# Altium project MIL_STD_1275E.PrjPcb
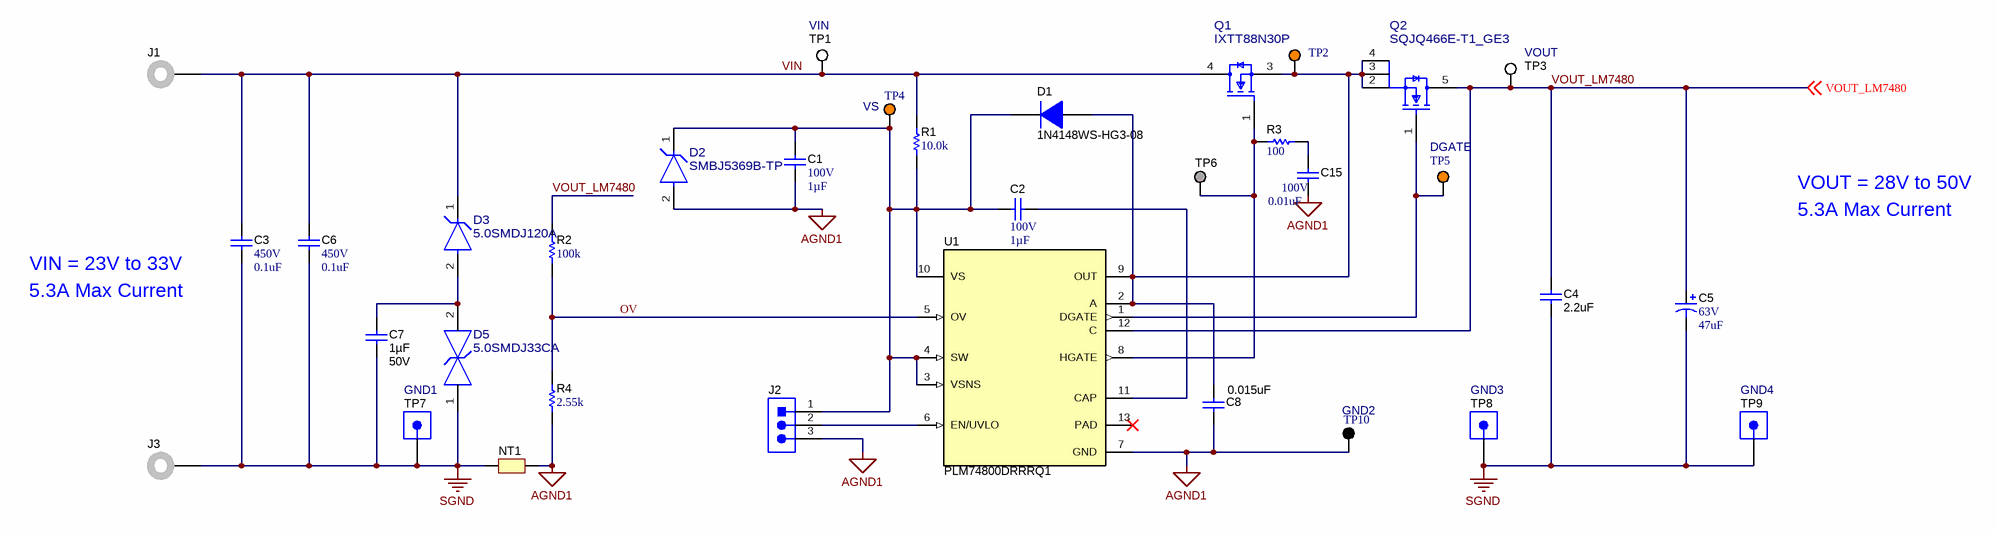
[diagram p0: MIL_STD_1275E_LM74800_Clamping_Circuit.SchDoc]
CopyrightYear: 2018; PCB_Layout: Albert Lo; PCB_Rev: E2; PRJ_Customer: Public Release; PRJ_Engineer: Albert Lo; PRJ_Number: MILSTD1275E; PRJ_Title: Change in menu Project|Project Options|Parameters; SCH_Rev: E2; TechSupport: http://www.ti.com/support; TID: N/A
3 sheets, 68 parts. Net scope: global (net labels, ports and power ports of the same name join across sheets).
Board file: MIL_STD_1275E.PcbDoc
Sheets:
  MIL_STD_1275E_LM74800_Clamping_Circuit.SchDoc
  MIL_STD_1275E_Hardware.SchDoc
  MIL_STD_1275E_LM5069_Clamping_Circuit.SchDoc

## Sheet MIL_STD_1275E_LM74800_Clamping_Circuit.SchDoc
size 431 x 279 mm; Date: Not shown in title block; ApprovedBy: Not shown in title block; CheckedBy: Not shown in title block; Author: Not shown in title block; CompanyName: Not shown in title block; Engineer: Not shown in title block; Organization: Not shown in title block; Address1: Not shown in title block; Address2: Not shown in title block; Address3: Not shown in title block; Address4: Not shown in title block; DocumentNumber: 1; Revision: Use project parameter SCH_Rev; SheetNumber: 1; SheetTotal: 4; PageSetup: Record=PageOptions¦CenterHorizontal=True¦CenterVertical=True¦PrintScale=1.00¦XCorrection=1.00¦YCorrection=1.00¦PrintKind=0¦BorderSize=5000000¦LeftOffset=0¦BottomOffset=0¦Orientation=2¦PaperLength=1000¦PaperWidth=1000¦Scale=100¦PaperSource=15¦PrintQuality=600¦MediaType=1¦DitherType=10¦PaperKind=Letter¦PrintScaleMode=1

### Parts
C1  VDC_V: 100V  Cap_F: 1µF  [0805_150]  (hidden comment: 08051C105K4Z2A)
C2  VDC_V: 100V  Cap_F: 1µF  [0805_150]  (hidden comment: 08051C105K4Z2A)
C3  VDC_V: 450V  ValueDisplayed: 0.1uF  [1206_180]  (hidden comment: C3216X7T2W104M160AE)
C4  ValueDisplayed: 2.2uF  [1210_210]  (hidden comment: CMP-0009084-1)
C5  VDC_V: 63V  ValueDisplayed: 47uF  [CAPSMT_62_HA0]  (hidden comment: EMVE630ADA470MHA0G)
C6  VDC_V: 450V  ValueDisplayed: 0.1uF  [1206_180]  (hidden comment: C3216X7T2W104M160AE)
C7  Cap_F: 1µF  VDC_V: 50V  [0805L]  (hidden comment: CGA4J3X7R1H105K125AB)
C8  value 0.015uF  [0603L]  (hidden comment: CGA3E2X7R2A153K080AA)
C15  VDC_V: 100V  ValueDisplayed: 0.01uF  [0402L]  (hidden comment: CGA2B3X7S2A103K050BB)
D1  1N4148WS-HG3-08  [SOD-323]
D2  SMBJ5369B-TP  [FP-SMBJ5369B-TP_SMB-MFG]
D3  5.0SMDJ120A  [FP-SMDJ120A_DO214AB-MFG]
D5  5.0SMDJ33CA  [FP-5.0SMDJ33CA_DO214AB-MFG]
J1  CMP-0055166-2  [Keystone575-8]  (value not drawn)
J2  PEC03SAAN  [CONN_PEC03SAAN]  (value not drawn)
J3  CMP-0055166-2  [Keystone575-8]  (value not drawn)
NT1  Net-Tie  [NetTie_0402]  (value not drawn)  (net tie, no BOM)
Q1  IXTT88N30P  [FP-IXTT88N30P_TO-268AA-IPC_C]
Q2  SQJQ466E-T1_GE3  [FP-SQJQ466E-T1_GE3_PowerPAK 8 x 8L-MFG]
R1  ValueDisplayed: 10.0k  [2512_084]  (hidden comment: HVCB2512FDD10K0)
R2  ValueDisplayed: 100k  [0402L]  (hidden comment: ERJ-2RKF1003X)
R3  ValueDisplayed: 100  [0402L]  (hidden comment: CRCW0402100RJNED)
R4  ValueDisplayed: 2.55k  [0402L]  (hidden comment: CRCW04022K55FKED)
TP1  Note: VIN  [Testpoint_Keystone_Miniature]  (hidden comment: 5015)
TP2  5003  [Keystone5003]  (value not drawn)
TP3  Note: VOUT  [Testpoint_Keystone_Miniature]  (hidden comment: 5015)
TP4  Note: VS  [Keystone5003]  (hidden comment: 5003)
TP5  Note: DGATE  [Keystone5003]  (hidden comment: 5003)
TP6  TP_SM_1MM  [TP_SM_1MM]  (value not drawn)  (no BOM)
TP7  Note: GND1  [CONN_1040]  (hidden comment: CMP-0055161-1)
TP8  Note: GND3  [CONN_1040]  (hidden comment: CMP-0055161-1)
TP9  Note: GND4  [CONN_1040]  (hidden comment: CMP-0055161-1)
TP10  Note: GND2  [Keystone5001]  (hidden comment: 5001)
U1  PLM74800DRRRQ1  [DRR0012E]

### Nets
AGND1: C1.2 C8.2 C15.2 D2.2(ANODE) J2.3 NT1.2 R4.1 TP10.1 U1.7(GND)
SGND: C3.2 C4.2 C5.2(-) C6.2 C7.2 D5.1 J3.1 NT1.1 TP7.1 TP8.1 TP9.1
OV: R2.1 R4.2 U1.5(OV)
VIN: C3.1 C6.1 D3.1(CATHODE) J1.1 Q1.4(Drain) R1.2 TP1.1
VOUT_LM7480: C4.1 C5.1(+) Q2.5(D) R2.2 TP3.1 U1.12(C) ; off-sheet VOUT_LM7480
NetC1_1: C1.1 C2.1 D1.1(K) D2.1(CATHODE) J2.1 R1.1 TP4.1 U1.3(VSNS) U1.4(SW) U1.10(VS)
NetC2_2: C2.2 U1.11(CAP)
NetC7_1: C7.1 D3.2(ANODE) D5.2
NetC8_1: C8.1 D1.2(A) Q1.3(Source) Q2.2(S) Q2.3(S) Q2.4(S) TP2.1 U1.2(A) U1.9(OUT)
NetC15_1: C15.1 R3.2
NetJ2_2: J2.2 U1.6(EN/UVLO)
NetQ1_1: Q1.1(Gate) R3.1 TP6.1 U1.8(HGATE)
NetQ2_1: Q2.1(G) TP5.1 U1.1(DGATE)

Not connected (* = marked no-connect by the designer): U1 13(PAD)*

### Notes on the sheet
- 5.3A Max Current
- VOUT = 28V to 50V
- VIN = 23V to 33V

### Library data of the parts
C1 C2 = CMP-0861070-1: CAP, CERM, 1 µF, 100 V,+/- 10%, X7R, AEC-Q200 Grade 1, 0805; Manufacturer: AVX; SizeZ_mm: 1.5; Polarized: N; TaMax_C: 125°C; TaMin_C: -55°C; Value: 1uF; AEC Qualified: Y; U/M: EA; AEC Grade: 1; Cap_Case: 0805; SizeX_mm: 2; SizeArea_mm2: 2.5; SizeAreaWB_mm2: 6.75; AEC Category: Q200; SizeY_mm: 1.25
C3 C6 = CMP-0008730-2: CAP, CERM, 0.1 uF, 450 V, +/- 20%, X7T, 1206; Manufacturer: TDK; TaMin_C: -55°C; Polarized: N; SizeAreaWB_mm2: 10.92; Value1: Unknown; U/M: EA; Value: 0.1uF; TaMax_C: 125°C; SizeZ_mm: 1.8; SizeX_mm: 3.2; SizeY_mm: 1.6; Cap_Case: 1206; SizeArea_mm2: 5.12; Cap_F: 100nF; AEC Category: Q200
C4 = CMP-0009084-1: CAP, CERM, 2.2 uF, 100 V, +/- 10%, X7R, 1210; PartNumber: C1210C225K1RACTU; Manufacturer: Kemet; Polarized: N; CompType: Capacitor; Value: 2.2uF; U/M: EA; Cap_F: 2.2µF; Value1: Unknown; VDC_V: 100V; TaMin_C: -55°C; TaMax_C: 125°C; Cap_Case: 1210; SizeArea_mm2: 8; SizeAreaWB_mm2: 14.7; SizeX_mm: 3.2; SizeY_mm: 2.5; SizeZ_mm: 2.1; AEC Category: Q200
C5 = CMP-0011301-2: CAP, AL, 47 uF, 63 V, +/- 20%, SMD; Manufacturer: Chemi-Con; TaMin_C: -40°C; Polarized: Y; SizeAreaWB_mm2: 106.09; Value1: Unknown; U/M: EA; Value: 47uF; TaMax_C: 105°C; SizeZ_mm: 10; SizeX_mm: 8.3; Cap_Case: HA0; SizeArea_mm2: 68.89; CompType: Capacitor; Cap_F: 47µF; IRMS_A: 170mA; AEC Category: Q200
C7 = CMP-0007976-2: CAP, CERM, 1 uF, 50 V, +/- 10%, X7R, AEC-Q200 Grade 1, 0805; Manufacturer: TDK; TaMin_C: -55°C; ESR_ohm: 8.782m; Polarized: N; SizeAreaWB_mm2: 6.75; Value1: 0.008782 ohm; U/M: EA; Value: 1uF; TaMax_C: 125°C; SizeZ_mm: 1.45; SizeX_mm: 2; SizeY_mm: 1.25; Cap_Case: 0805; SizeArea_mm2: 2.5; AEC Qualified: Y; IRMS_A: 2.20488A; AEC Grade: 1; AEC Category: Q200
C8 = CMP-0007084-4: CAP, CERM, 0.015 uF, 100 V, +/- 10%, X7R, AEC-Q200 Grade 1, 0603; Manufacturer: TDK; TaMin_C: -55°C; ESR_ohm: 0.128703; Polarized: N; SizeAreaWB_mm2: 4.68; Value1: 0.128703 ohm; U/M: EA; TaMax_C: 125°C; SizeZ_mm: 1; SizeX_mm: 1.6; SizeY_mm: 0.8; Cap_Case: 0603; Value2: 100V; SizeArea_mm2: 1.28; AEC Qualified: Y; Cap_F: 15nF; IRMS_A: 506.826mA; AEC Category: Q200
C15 = CMP-0006333-2: CAP, CERM, 0.01 uF, 100 V, +/- 10%, X7S, AEC-Q200 Grade 1, 0402; Manufacturer: TDK; TaMin_C: -55°C; ESR_ohm: 0.4102; Polarized: N; SizeAreaWB_mm2: 3; Value1: 0.410191 ohm; U/M: EA; Value: 0.01uF; TaMax_C: 125°C; SizeZ_mm: 0.6; SizeX_mm: 1; SizeY_mm: 0.5; Cap_Case: 0402; AEC Qualified: Y; Cap_F: 10nF; IRMS_A: 291.729mA; AEC Category: Q200
D1 = CMP-0860225-1: Diode, Switching, 100 V, 150 A, AEC-Q101, SOD-323; Manufacturer: Vishay-Semiconductor; Vf_V: 1.2V; TJmax_C: 150°C; Value: 100V; SizeX_mm: 2.7; SizeZ_mm: 1; Io_A: 150A; SizeAreaWB_mm2: 8.695; AEC Qualified: Y; SizeY_mm: 1.35; SizeArea_mm2: 3.645; AEC Category: Q101
D2 = CMP-0095181-1: Zener Diode 51 V 5 W ±5% Surface Mount DO-214AA (SMB); Manufacturer: MCC; Standoff Height: 0.05mm; Zener Impedance: 27Ω; AEC Qualified: No; Vr_V: 0.9V; SizeZ_mm: 2.62mm; Vz_V: 51V; Power_W: 5W; TJmax_C: +150°C; Forward Current: 1mA
D3 = CMP-0093492-1: Diode TVS Single Uni-Dir 120V 5KW 2-Pin DO-214AB; Manufacturer: Littelfuse Inc; Ipp: 26A; Direction: Unidirectional; AEC Qualified: No; TJmax_C: +150°C; Number Of Channels: 1; SizeZ_mm: 2.62mm; Breakdown Voltage: 133V; Clamping Voltage: 193V
D5 = CMP-0093617-1: 53.3V Clamp 93.9A Ipp Tvs Diode Surface Mount DO-214AB (SMCJ); Manufacturer: Littelfuse; Ppk: 5kW; AEC Qualified: No; VRWM: 33V; TJmax_C: +150°C; SizeZ_mm: 2.62mm; Breakdown Voltage: 36.7V; Number Of Channels: 1; Direction: Bidirectional
J1 J3 = CMP-0055166-2: Standard Banana Jack, Uninsulated, 8.9mm; PartNumber: 575-8; Manufacturer: Keystone; CT: TRUE; Green_REACh: Passed; CNHeader: FALSE; Green_Lifecycle: Active
J2 = CMP-0002338-1: Header, 100mil, 3x1, Tin, TH; Manufacturer: Sullins Connector Solutions; CNHeader: TRUE; Current_A: 3A; Green_Lifecycle: Not Set; Shrouded: N; Gender: Male; Green_REACh: Incomplete; Voltage_V: 1.8kV; Row_Count: 1; Pitch_mm: 2.54; CT: FALSE; Cert_UL: Y
NT1 = CMP-0078142-4: Single point connection between nets.
Q1 = CMP-0093697-1: N-Channel 300 V 88A (Tc) 600W (Tc) Surface Mount TO-268AA; Manufacturer: Littlefuse; VdsMax_V: 1.5V; QgTyp_nC: 180nC @ 10V; Transconductance: 60S; Turn On Delay Time: 25ns; Threshold Vgs Min: 2.5V; AEC Qualified: No; Reverse Recovery Time: 250ns; Vgs_V: 20V; SizeZ_mm: 5.35mm; Turn Off Delay Time: 96ns; Standoff Height: 0.02mm; Reverse Recovery Charge: 3300nC; ChMode: False; Rdson45_ohm: 40m; Threshold Vgs Max: 5V; TJmax_C: +150°C; Number Of N Channels: 1; Pulse Drain Current: 220A; Input Capacitace At Vds: 6300pF @ 25V; Drain To Source Breakdown Voltage: 300V
Q2 = CMP-0093493-1: N-Channel 60 V 200A (Tc) 150W (Tc) Surface Mount PowerPAK® 8 x 8; Manufacturer: Vishay; AEC Grade: Grade 0; Pulse Drain Current: 500A; SizeZ_mm: 2.03mm; Rthja Max: 50°C/W; TJmax_C: +175°C; Typ Forward Diode Voltage: 0.82V; Input Capacitace At Vds: 8170pF @ 25V; Vgs_V: 20V; Turn Off Delay Time: 47ns; VdsMax_V: 1.2V; Standoff Height: 0mm; AEC Qualified: Yes; Turn On Delay Time: 24ns; Number Of N Channels: 1; Drain To Source Breakdown Voltage: 60V; QgTyp_nC: 135nC @ 10V; ChMode: False; Transconductance: 140S; Threshold Vgs Min: 2.5V; Threshold Vgs Max: 3.5V; Rdson45_ohm: 1.7m
R1 = CMP-0015824-1: RES, 10.0 k, 1%, 2 W, 2512; Manufacturer: Stackpole Electronics Inc; Power_W: 2W; TempCo: 100 ppm/C; Value_Code: 10k0; U/M: EA; Value: 10.0k; EIA_Code: E96; Res_ohm: 10k; VDC_V: 2.5kV; AEC Category: Q200
R2 = CMP-0026659-2: RES, 100 k, 1%, 0.1 W, 0402; Manufacturer: Panasonic; Power_W: 100mW; TempCo: 100 ppm/C; U/M: EA; Value: 100k; EIA_Code: E96; SizeX_mm: 1; SizeY_mm: 0.5; SizeZ_mm: 0.6; Value2: 0.1W; AEC Qualified: Yes; VDC_V: 50V; AEC Category: Q200; AEC Grade: 0
R3 = CMP-0026824-3: RES, 100, 5%, 0.063 W, AEC-Q200 Grade 0, 0402; Manufacturer: Vishay-Dale; Power_W: 63mW; TempCo: 200 ppm/C; Value_Code: 100R; Value: 100; EIA_Code: E24; SizeX_mm: 1; SizeY_mm: 0.5; SizeZ_mm: 0.6; Value2: 0.063W; AEC Qualified: Y; VDC_V: 50V; AEC Category: Q200; AEC Grade: 0
R4 = CMP-0026238-2: RES, 2.55 k, 1%, 0.063 W, AEC-Q200 Grade 0, 0402; Manufacturer: Vishay-Dale; Power_W: 63mW; TempCo: 100 ppm/C; Value_Code: 2k55; Value: 2.55k; EIA_Code: E96; SizeX_mm: 1; SizeY_mm: 0.5; SizeZ_mm: 0.6; Value2: 0.063W; AEC Qualified: Y; VDC_V: 50V; AEC Category: Q200; AEC Grade: 0
TP1 TP3 = 5015: Test Point, Miniature, SMT; Manufacturer: Keystone; CompType: Test Point Loop
TP2 = CMP-0055140-1: Test Point, Miniature, Orange, TH; Manufacturer: Keystone; CNHeader: FALSE; Green_Lifecycle: Active; Green_REACh: Passed; ContactFinish: Silver; CT: TRUE; Note: HGATE
TP4 TP5 = CMP-0055140-1: Test Point, Miniature, Orange, TH; Manufacturer: Keystone; CNHeader: FALSE; Green_Lifecycle: Active; Green_REACh: Passed; ContactFinish: Silver; CT: TRUE
TP6 = CMP-0003825-1: 1mm Test Point, SMT; Manufacturer: Any
TP7-TP9 = CMP-0055161-1: TEST POINT SLOTTED .118", TH; PartNumber: 1040; Manufacturer: Keystone; CNHeader: FALSE; Green_Lifecycle: Active; Green_REACh: Passed; CT: TRUE
TP10 = CMP-0055138-1: Test Point, Miniature, Black, TH; Manufacturer: Keystone; CNHeader: FALSE; Green_Lifecycle: Active; Green_REACh: Passed; ContactFinish: Silver; CT: TRUE
U1 = CMP-0860384-3: Ideal Diode Controller with Load Dump Protection, DRR0012E (WSON-12); Manufacturer: Texas Instruments; AEC Category: Q200; SizeY_mm: 3; SizeArea_mm2: 9; CompType: IC; SizeZ_mm: 0.8; AEC Qualified: Y; SizeAreaWB_mm2: 16

## Sheet MIL_STD_1275E_Hardware.SchDoc
size 431 x 279 mm; Date: Not shown in title block; ApprovedBy: Not shown in title block; CheckedBy: Not shown in title block; Author: Not shown in title block; CompanyName: Not shown in title block; Engineer: Not shown in title block; Organization: Not shown in title block; Address1: Not shown in title block; Address2: Not shown in title block; Address3: Not shown in title block; Address4: Not shown in title block; DocumentNumber: 3; Revision: Use project parameter SCH_Rev; SheetNumber: 3; SheetTotal: 4; PageSetup: Record=PageOptions¦CenterHorizontal=True¦CenterVertical=True¦PrintScale=1.00¦XCorrection=1.00¦YCorrection=1.00¦PrintKind=0¦BorderSize=5000000¦LeftOffset=0¦BottomOffset=0¦Orientation=2¦PaperLength=1000¦PaperWidth=1000¦Scale=100¦PaperSource=15¦PrintQuality=600¦MediaType=1¦DitherType=10¦PaperKind=Letter¦PrintScaleMode=1
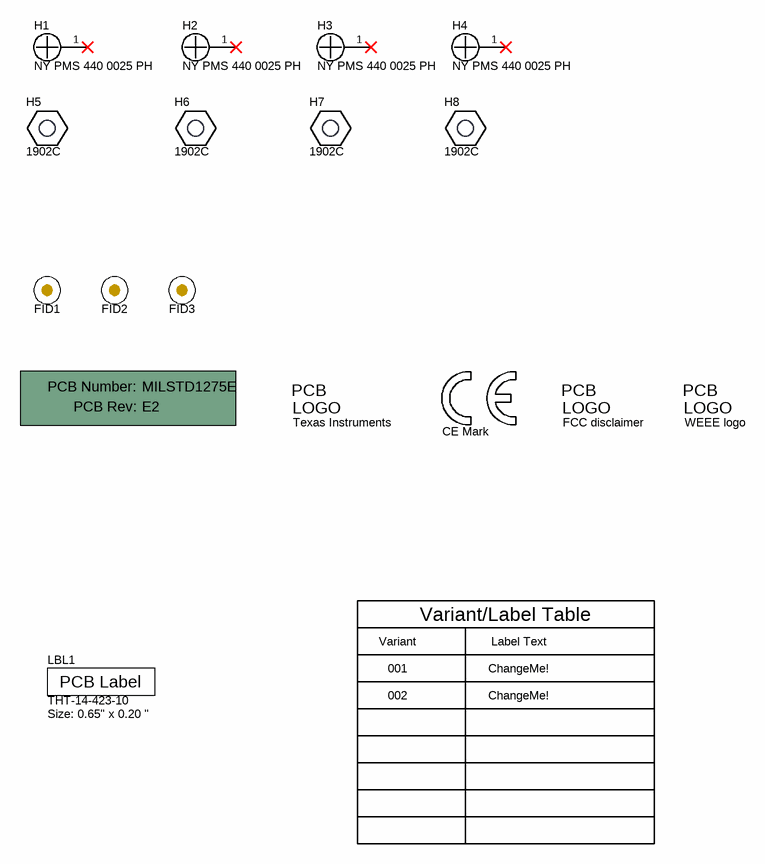
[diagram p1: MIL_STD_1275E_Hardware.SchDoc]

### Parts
!PCB1  Printed Circuit Board  (value not drawn)  (mechanical)
FID1  Fiducial  [Fiducial10-20]  (value not drawn)
FID2  Fiducial  [Fiducial10-20]  (value not drawn)
FID3  Fiducial  [Fiducial10-20]  (value not drawn)
H1  NY PMS 440 0025 PH  [NY PMS 440 0025 PH]
H2  NY PMS 440 0025 PH  [NY PMS 440 0025 PH]
H3  NY PMS 440 0025 PH  [NY PMS 440 0025 PH]
H4  NY PMS 440 0025 PH  [NY PMS 440 0025 PH]
H5  1902C  [Keystone_1902C]
H6  1902C  [Keystone_1902C]
H7  1902C  [Keystone_1902C]
H8  1902C  [Keystone_1902C]
LBL1  THT-14-423-10  Note: Size: 0.65" x 0.20 "  [Label_650x200]
Logo1  CE Mark  [CE_Mark_5mm]  (no BOM)
Logo2  Texas Instruments  [TI_Stacked_Overlay_Small]  (no BOM)
Logo3  FCC disclaimer  [FCC_disclaimer]  (no BOM)
Logo4  WEEE logo  [WEEE_Minimum]  (no BOM)

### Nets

Not connected (* = marked no-connect by the designer): H1 1*; H2 1*; H3 1*; H4 1*

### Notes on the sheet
- Variant
- Variant/Label Table
- Label Text
- 001
- 002
- ChangeMe!

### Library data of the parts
!PCB1 = CMP-0003618-2: Manufacturer: Any; PartNumber: MILSTD1275E
FID1-FID3 = CMP-0077181-1: Fiducial mark.  There is nothing to buy or mount.
H1-H4 = CMP-0003617-1: Machine Screw, Round, #4-40 x 1/4, Nylon, Philips panhead; Manufacturer: B&F Fastener Supply; CompType: Hardware
H5-H8 = CMP-0003610-1: Standoff, Hex, 0.5"L #4-40 Nylon; Manufacturer: Keystone; CompType: Hardware
LBL1 = CMP-0003625-1: Thermal Transfer Printable Labels, 0.650" W x 0.200" H - 10,000 per roll; Manufacturer: Brady; CompType: Label
Logo1 = CMP-0074844-1: SymbolCreator: a0412235
Logo2 = CMP-0074838-1: Texas Instrument Corporate Signature; SymbolCreator: a0412235; Lib Reference: TI_Logo; Library Reference: Logo
Logo3 = CMP-0074847-1: FCC_disclaimer; Library Reference: Logo
Logo4 = CMP-0074769-1

## Sheet MIL_STD_1275E_LM5069_Clamping_Circuit.SchDoc
size 431 x 279 mm; Date: Not shown in title block; ApprovedBy: Not shown in title block; CheckedBy: Not shown in title block; Author: Not shown in title block; CompanyName: Not shown in title block; Engineer: Not shown in title block; Organization: Not shown in title block; Address1: Not shown in title block; Address2: Not shown in title block; Address3: Not shown in title block; Address4: Not shown in title block; DocumentNumber: 2; Revision: Use project parameter SCH_Rev; SheetNumber: 2; SheetTotal: 4; PageSetup: Record=PageOptions¦CenterHorizontal=True¦CenterVertical=True¦PrintScale=1.00¦XCorrection=1.00¦YCorrection=1.00¦PrintKind=0¦BorderSize=5000000¦LeftOffset=0¦BottomOffset=0¦Orientation=2¦PaperLength=1000¦PaperWidth=1000¦Scale=100¦PaperSource=15¦PrintQuality=600¦MediaType=1¦DitherType=10¦PaperKind=Letter¦PrintScaleMode=1
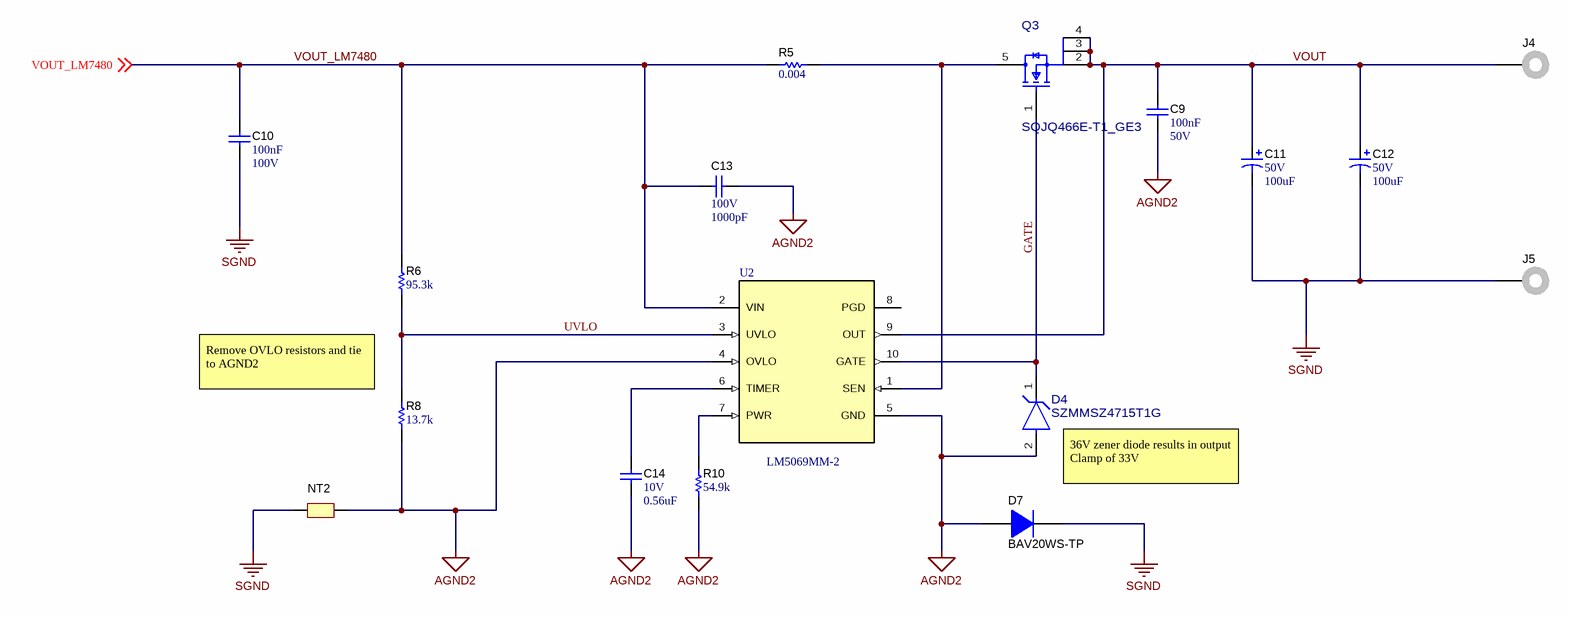
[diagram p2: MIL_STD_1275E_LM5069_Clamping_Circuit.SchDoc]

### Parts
C9  Cap_F: 100nF  VDC_V: 50V  [0603L]  (hidden comment: C0603C104J5RACTU)
C10  Cap_F: 100nF  VDC_V: 100V  [0603L]  (hidden comment: GRM188R72A104KA35D)
C11  VDC_V: 50V  ValueDisplayed: 100uF  [Panasonic_D8]  (hidden comment: EEEFTH101XAP)
C12  VDC_V: 50V  ValueDisplayed: 100uF  [Panasonic_D8]  (hidden comment: EEEFTH101XAP)
C13  VDC_V: 100V  ValueDisplayed: 1000pF  [0402L]  (hidden comment: GRM155R72A102KA01D)
C14  VDC_V: 10V  ValueDisplayed: 0.56uF  [0402L]  (hidden comment: GRM155R61A564KE15D)
D4  SZMMSZ4715T1G  [FP-SZMMSZ4715T1G_SOD123-MFG]
D7  BAV20WS-TP  [SOD-323]
J4  CMP-0055166-2  [Keystone575-8]  (value not drawn)
J5  CMP-0055166-2  [Keystone575-8]  (value not drawn)
NT2  Net-Tie  [NetTie_0402]  (value not drawn)  (net tie, no BOM)
Q3  SQJQ466E-T1_GE3  [FP-SQJQ466E-T1_GE3_PowerPAK 8 x 8L-MFG]
R5  ValueDisplayed: 0.004  [1206]  (hidden comment: CRF1206-FZ-R004ELF)
R6  ValueDisplayed: 95.3k  [0402L]  (hidden comment: CRCW040295K3FKED)
R8  ValueDisplayed: 13.7k  [0402L]  (hidden comment: CRCW040213K7FKED)
R10  ValueDisplayed: 54.9k  [0402L]  (hidden comment: CRCW040254K9FKED)
U2  LM5069MM-2  [DGS0010A_N]

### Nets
AGND2: C9.2 C13.1 C14.2 D4.2(ANODE) D7.2(A) NT2.2 R8.1 R10.1 U2.4(OVLO) U2.5(GND)
SGND: C10.2 C11.2(-) C12.2(-) D7.1(K) J5.1 NT2.1
GATE: D4.1(CATHODE) Q3.1(G) U2.10(GATE)
UVLO: R6.1 R8.2 U2.3(UVLO)
VOUT: C9.1 C11.1(+) C12.1(+) J4.1 Q3.2(S) Q3.3(S) Q3.4(S) U2.9(OUT)
VOUT_LM7480: C10.1 C13.2 R5.1 R6.2 U2.2(VIN) ; off-sheet VOUT_LM7480
NetC14_1: C14.1 U2.6(TIMER)
NetQ3_5: Q3.5(D) R5.2 U2.1(SEN)
NetR10_2: R10.2 U2.7(PWR)

Not connected (* = marked no-connect by the designer): U2 8(PGD)

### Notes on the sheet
- Remove OVLO resistors and tie to AGND2
- (near D4) 36V zener diode results in output Clamp of 33V

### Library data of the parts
C9 = CMP-0006858-4: CAP, CERM, 0.1 uF, 50 V, +/- 5%, X7R, 0603; Manufacturer: Kemet; TaMin_C: -55°C; Polarized: N; SizeAreaWB_mm2: 4.68; Value1: Unknown; U/M: EA; Value: 0.1uF; TaMax_C: 125°C; SizeZ_mm: 1; SizeX_mm: 1.6; SizeY_mm: 0.8; Cap_Case: 0603; SizeArea_mm2: 1.28; AEC Category: Q200
C10 = CMP-0007469-4: CAP, CERM, 0.1 uF, 100 V, +/- 10%, X7R, 0603; Manufacturer: MuRata; TaMin_C: -55°C; Polarized: N; SizeAreaWB_mm2: 4.68; Value1: Unknown; U/M: EA; Value: 0.1uF; TaMax_C: 125°C; SizeZ_mm: 1; SizeX_mm: 1.6; SizeY_mm: 0.8; Cap_Case: 0603; SizeArea_mm2: 1.28; AEC Category: Q200
C11 C12 = CMP-0011205-1: CAP, AL, 100 uF, 50 V, +/- 20%, 0.34 ohm, AEC-Q200 Grade 2, SMD; Manufacturer: Panasonic; TaMin_C: -55°C; ESR_ohm: 0.34; Polarized: Y; SizeAreaWB_mm2: 73.96; U/M: EA; Value: 100uF; TaMax_C: 105°C; SizeZ_mm: 8; SizeX_mm: 6.6; Cap_Case: 6.3x7.7mm; SizeArea_mm2: 43.56; CompType: Capacitor; Cap_F: 100µF; IRMS_A: 350mA; AEC Grade: 2; AEC Category: Q200
C13 = CMP-0006699-1: CAP, CERM, 1000 pF, 100 V, +/- 10%, X7R, 0402; Manufacturer: MuRata; TaMin_C: -55°C; Polarized: N; SizeAreaWB_mm2: 3; Value1: Unknown; U/M: EA; Value: 1000pF; TaMax_C: 125°C; SizeZ_mm: 0.6; SizeX_mm: 1; SizeY_mm: 0.5; Cap_Case: 0402; Cap_F: 1nF; AEC Category: Q200
C14 = CMP-0006584-2: CAP, CERM, 0.56 uF, 10 V, +/- 10%, X5R, 0402; Manufacturer: MuRata; TaMin_C: -55°C; Polarized: N; SizeAreaWB_mm2: 3; Value1: Unknown; U/M: EA; Value: 0.56uF; TaMax_C: 85°C; SizeZ_mm: 0.6; SizeX_mm: 1; SizeY_mm: 0.5; Cap_Case: 0402; Cap_F: 560nF; AEC Category: Q200
D4 = CMP-0094040-1: Zener Diode 36 V 500 mW - Surface Mount SOD-123; Manufacturer: On Semiconductor; Power_W: 500mW; Vf_V: 37.8V; Standoff Height: 0mm; AEC Qualified: Yes; Ciiva Ids: 807476; TJmax_C: 150°C; AEC Grade: Grade 0; SizeZ_mm: 1.35mm; Max Reverse Leakage Current: 0.01uA; Vz_V: 36V; Import Ts: 1521868983; Vr_V: 27.3V
D7 = CMP-0029044-2: Diode, P-N, 150 V, 0.2 A, SOD-323; Manufacturer: Micro Commercial Components; Value2: 1.25V; AEC Category: Q101; SizeArea_mm2: 3.645; Vr_V: 150V; Green_REACh: Incomplete; SizeZ_mm: 1; Green_Lifecycle: Not Set; TJmax_C: 150°C; SizeAreaWB_mm2: 8.695; Value1: 0.2A; SizeX_mm: 2.7; Io_A: 200mA; SizeY_mm: 1.35; Value: 150V
J4 J5 = CMP-0055166-2: as J1 on sheet MIL_STD_1275E_LM74800_Clamping_Circuit
NT2 = CMP-0078142-4: Single point connection between nets.
Q3 = CMP-0093493-1: as Q2 on sheet MIL_STD_1275E_LM74800_Clamping_Circuit
R5 = CMP-0078823-1: RES, 0.004, 1%, 1 W, AEC-Q200 Grade 0, 1206; Manufacturer: Bourns; Value_Code: 4L000; SizeArea_mm2: 5.12; AEC Qualified: Y; AEC Category: Q200; Res_ohm: 4m; Value: 0.004; SizeZ_mm: 1.35; TempCo: 50 ppm/C; AEC Grade: 0; SizeY_mm: 1.6; Power_W: 1W; SizeX_mm: 3.2
R6 = CMP-0026613-3: RES, 95.3 k, 1%, 0.063 W, AEC-Q200 Grade 0, 0402; Manufacturer: Vishay-Dale; SizeX_mm: 1; Value: 95.3k; EIA_Code: E96; AEC Category: Q200; Value2: 0.063W; SizeY_mm: 0.5; SizeZ_mm: 0.6; Power_W: 63mW; VDC_V: 50V; AEC Qualified: Y; Value_Code: 95k3; TempCo: 100 ppm/C; AEC Grade: 0
R8 = CMP-0026005-3: RES, 13.7 k, 1%, 0.063 W, AEC-Q200 Grade 0, 0402; Manufacturer: Vishay-Dale; Power_W: 63mW; TempCo: 100 ppm/C; Value_Code: 13k7; Value: 13.7k; EIA_Code: E96; SizeX_mm: 1; SizeY_mm: 0.5; SizeZ_mm: 0.6; Value2: 0.063W; AEC Qualified: Y; VDC_V: 50V; AEC Category: Q200; AEC Grade: 0
R10 = CMP-0026449-2: RES, 54.9 k, 1%, 0.063 W, AEC-Q200 Grade 0, 0402; Manufacturer: Vishay-Dale; Power_W: 63mW; TempCo: 100 ppm/C; Value_Code: 54k9; Value: 54.9k; EIA_Code: E96; SizeX_mm: 1; SizeY_mm: 0.5; SizeZ_mm: 0.6; Value2: 0.063W; AEC Qualified: Y; VDC_V: 50V; AEC Category: Q200; AEC Grade: 0
U2 = CMP-0071870-1: Positive High Voltage Hot Swap / Inrush Current Controller with Power Limiting, 10-pin MSOP; Manufacturer: Texas Instruments; PackageTopMarking: ZXTT*SNBB; CompType: MiscPower; PowerWise: N

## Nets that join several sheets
SGND: MIL_STD_1275E_LM74800_Clamping_Circuit (11 pins), MIL_STD_1275E_LM5069_Clamping_Circuit (6 pins)
VOUT_LM7480: MIL_STD_1275E_LM74800_Clamping_Circuit (6 pins), MIL_STD_1275E_LM5069_Clamping_Circuit (5 pins)

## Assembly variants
001: not fitted C1 FID1 FID2 FID3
